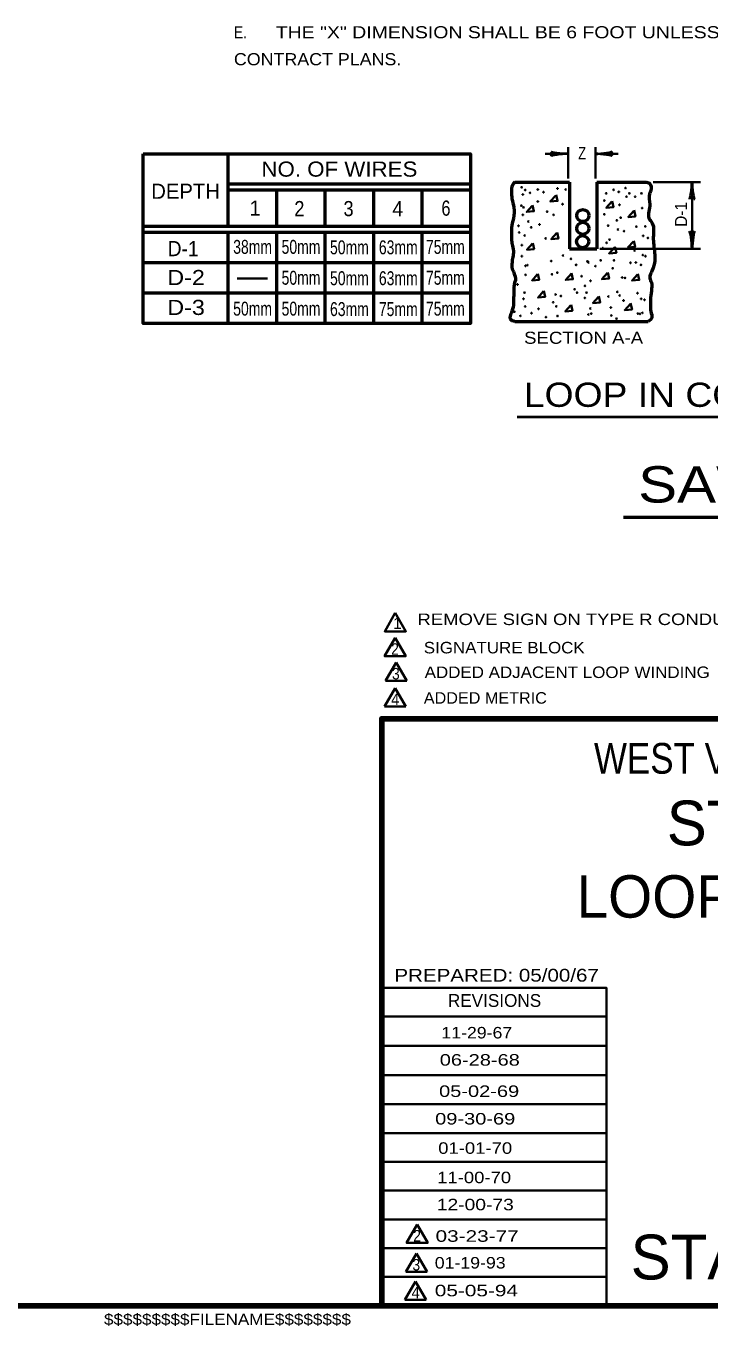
# Model space of a CAD drawing. Extents: x -90 to 623, y -379 to 75.
# Drawn here: x 376.8 to 489.7, y -372.3 to -157.7 of the extents above; entities that cross this region are included whole.
import ezdxf
from ezdxf.enums import TextEntityAlignment as Align

# ---------------------------------------------------------------- set-up
doc = ezdxf.new("R2010")
doc.units = 0
doc.header["$LTSCALE"] = 0.8
doc.layers.add('1', color=7, linetype='Continuous', lineweight=35)

msp = doc.modelspace()

# ---------------------------------------------------------------- linework, layer by layer
at = {"layer": '1'}
for p, q in [((466.3032, -182.8762), (466.3032, -177.7043)), ((470.8032, -182.8762), (470.8032, -177.7043)), ((462.4751, -178.8182), (466.2951, -178.8182)), ((470.7501, -178.8182), (474.5701, -178.8182)), ((480.2982, -183.5127), (488.1103, -183.5127)), ((486.7431, -183.4331), (486.7431, -194.4942)), ((471.5457, -194.493), (488.1103, -194.493)), ((411.6715, -199.4072), (416.6715, -199.4072)), ((437.8979, -262.8001), (436.1479, -265.8312)), ((439.6479, -265.8312), (437.8979, -262.8001)), ((436.1479, -265.8312), (439.6479, -265.8312)), ((437.7568, -267.038), (436.0068, -270.0691)), ((439.5068, -270.0691), (437.7568, -267.038)), ((436.0068, -270.0691), (439.5068, -270.0691)), ((472.6105, -321.2478), (435.5272, -321.2478)), ((472.6105, -326.0812), (435.5272, -326.0812)), ((472.6105, -330.9145), (435.5272, -330.9145)), ((472.6105, -335.7478), (435.5272, -335.7478)), ((472.6105, -340.4978), (435.5272, -340.4978)), ((472.6105, -345.2478), (435.5272, -345.2478)), ((472.6105, -349.9978), (435.5272, -349.9978)), ((472.6105, -354.7478), (435.5272, -354.7478)), ((472.6105, -359.4978), (435.5272, -359.4978)), ((441.2536, -360.3902), (439.5036, -363.4213)), ((443.0036, -363.4213), (441.2536, -360.3902)), ((472.6105, -364.2478), (435.5272, -364.2478)), ((439.5036, -363.4213), (443.0036, -363.4213)), ((441.1125, -364.977), (439.3625, -368.0081)), ((442.8625, -368.0081), (441.1125, -364.977)), ((439.3625, -368.0081), (442.8625, -368.0081))]:
    msp.add_line(p, q, dxfattribs=at)
at = {"layer": '1', "lineweight": 53}
for p, q in [((410.1558, -178.8394), (410.1558, -190.7343)), ((418.1558, -178.8394), (418.1558, -178.8787)), ((426.1558, -178.8394), (426.1558, -178.8787)), ((434.1558, -178.8394), (434.1558, -178.8787)), ((442.1558, -178.8394), (442.1558, -178.9583)), ((450.1558, -183.8394), (410.1597, -183.8394)), ((457.5023, -183.4934), (466.5023, -183.4934)), ((466.5023, -183.4934), (466.5023, -194.4934)), ((471.0023, -183.4934), (479.0023, -183.4934)), ((471.0023, -183.4934), (471.0023, -194.4934)), ((450.1558, -184.8394), (410.1597, -184.8394)), ((418.1558, -184.8463), (418.1558, -190.8138)), ((426.1558, -184.9259), (426.1558, -190.7343)), ((434.1558, -184.9259), (434.1558, -190.8138)), ((442.1558, -184.8463), (442.1558, -190.7343)), ((450.1558, -190.8394), (396.1558, -190.8394)), ((450.1558, -191.8394), (396.1558, -191.8394)), ((410.1558, -191.9278), (410.1558, -206.8394)), ((418.1558, -191.8483), (418.1558, -206.8394)), ((426.1558, -191.9278), (426.1558, -206.8394)), ((434.1558, -191.8483), (434.1558, -206.8394)), ((442.1558, -191.8483), (442.1558, -206.8394)), ((466.5023, -194.4934), (471.0023, -194.4934)), ((450.1558, -196.8394), (396.1558, -196.8394)), ((450.1558, -201.8394), (396.1558, -201.8394)), ((457.5023, -206.4934), (479.5023, -206.4934)), ((475.4047, -238.811), (566.749, -238.811))]:
    msp.add_line(p, q, dxfattribs=at)
at = {"layer": '1', "lineweight": 40}
msp.add_line((457.8999, -222.2609), (520.5994, -222.2609), dxfattribs=at)
at = {"layer": '1', "lineweight": 158}
msp.add_line((617.1938, -368.9978), (-42.4728, -368.9978), dxfattribs=at)
at = {"layer": '1', "lineweight": 53}
msp.add_lwpolyline([(396.1558, -178.8394), (450.1558, -178.8394), (450.1558, -206.8394), (396.1558, -206.8394)], close=True, dxfattribs=at)
at = {"layer": '1'}
for points in [[(464.2712, -185.679), (463.3498, -186.7155), (464.5398, -186.6003), (464.3095, -185.6022)], [(473.501, -186.7134), (472.5797, -187.7499), (473.7697, -187.6347), (473.5393, -186.6367)], [(460.3724, -187.3897), (459.4511, -188.4262), (460.6411, -188.3111), (460.4108, -187.313)], [(477.1213, -188.2252), (476.2, -189.2617), (477.39, -189.1465), (477.1597, -188.1484)], [(464.4303, -191.8852), (463.509, -192.9218), (464.699, -192.8066), (464.4687, -191.8085)], [(460.4122, -193.6358), (459.4908, -194.6722), (460.6808, -194.5571), (460.4505, -193.559)], [(473.9784, -194.2325), (473.0571, -195.269), (474.2471, -195.1538), (474.0168, -194.1557)], [(477.0816, -193.2777), (476.1602, -194.3142), (477.3502, -194.1991), (477.1199, -193.201)], [(461.2476, -198.6883), (460.3262, -199.7248), (461.5162, -199.6097), (461.2859, -198.6116)], [(466.8173, -198.6087), (465.896, -199.6453), (467.086, -199.5301), (466.8557, -198.532)], [(472.7849, -198.4894), (471.8636, -199.5259), (473.0536, -199.4108), (472.8232, -198.4127)], [(477.7578, -198.7281), (476.8365, -199.7646), (478.0265, -199.6494), (477.7962, -198.6513)], [(462.2423, -201.5129), (461.3209, -202.5494), (462.5109, -202.4342), (462.2806, -201.4362)], [(466.7378, -203.8204), (465.8164, -204.8569), (467.0064, -204.7417), (466.7761, -203.7437)], [(471.3129, -202.428), (470.3916, -203.4645), (471.5816, -203.3493), (471.3512, -202.3512)], [(476.5643, -203.5817), (475.643, -204.6182), (476.833, -204.503), (476.6027, -203.5049)], [(472.6105, -368.9978), (472.6105, -316.4978), (435.5272, -316.4978)]]:
    msp.add_lwpolyline(points, dxfattribs=at)
for points in [[(437.7648, -254.6303), (436.0148, -257.6614), (439.5148, -257.6614)], [(437.7527, -258.7338), (436.0027, -261.7649), (439.5027, -261.7649)], [(441.3798, -355.5983), (439.6298, -358.6294), (443.1298, -358.6294)]]:
    msp.add_lwpolyline(points, close=True, dxfattribs=at)
at = {"layer": '1', "lineweight": 158}
msp.add_lwpolyline([(435.5272, -368.9978), (435.5272, -272.0812), (617.1938, -272.0812)], dxfattribs=at)
at = {"layer": '1'}
for centre in [(458.6103, -184.3565), (464.538, -184.5554), (475.757, -184.4758), (458.8092, -185.55), (459.207, -184.7941), (460.0027, -185.2715), (461.2757, -184.7146), (461.2757, -186.7037), (462.2305, -185.1522), (465.8907, -184.7146), (472.256, -186.5446), (472.5743, -185.3511), (473.8076, -184.7543), (474.6431, -185.1124), (475.9162, -185.9081), (476.3936, -185.3511), (477.3483, -185.9081), (478.3827, -185.3511), (458.5704, -187.3801), (458.8092, -188.8918), (458.9285, -187.6586), (462.8273, -188.3747), (463.9014, -188.8918), (465.3734, -187.1413), (472.256, -188.8123), (474.7624, -187.2607), (478.5021, -187.7779), (458.093, -190.7219), (459.7242, -190.0058), (460.2016, -190.9606), (461.5542, -190.4832), (472.8926, -190.6821), (474.3247, -189.8068), (474.9613, -189.3692), (477.5472, -190.8413), (479.0192, -190.8015), (458.2124, -191.7961), (459.1274, -192.3132), (462.5886, -192.7907), (473.1312, -192.9896), (474.5238, -191.3187), (475.5183, -191.5972), (478.6612, -192.353), (479.4569, -192.7111), (458.65, -193.9046), (472.0173, -194.382), (472.6538, -193.5067), (477.2688, -194.7798), (458.65, -195.7347), (459.2467, -197.326), (459.565, -197.2067), (463.5036, -196.5303), (465.453, -195.6153), (466.7659, -196.1722), (467.6013, -197.1668), (469.4712, -196.5701), (469.6303, -196.769), (470.784, -197.3657), (471.6592, -196.411), (473.8474, -196.411), (476.5925, -196.8088), (477.4677, -196.769), (478.3032, -197.1668), (478.6214, -195.5358), (479.0591, -195.7347), (459.2865, -198.798), (463.623, -198.7184), (464.4982, -198.4399), (468.5163, -199.0367), (473.6485, -197.7238), (475.2, -199.2356), (475.6774, -199.3152), (457.9339, -200.3893), (459.0876, -201.742), (467.3627, -201.185), (467.7605, -201.742), (469.0733, -200.628), (469.312, -201.742), (469.9883, -199.7926), (474.4043, -201.6227), (458.9285, -202.7763), (463.8219, -203.3333), (464.2197, -202.0602), (465.095, -202.2989), (469.0336, -202.6172), (472.9323, -202.3785), (474.8022, -202.2194), (475.4387, -203.0548), (477.7462, -201.8216), (478.3429, -202.7763), (478.8999, -202.9355), (457.4167, -204.8849), (458.4113, -205.5613), (459.207, -204.0097), (460.2413, -205.1236), (461.3951, -204.4075), (462.6283, -205.7999), (464.3391, -204.0097), (464.538, -205.601), (469.6303, -205.3623), (469.9486, -204.3678), (470.1078, -205.2032), (473.3302, -204.2086), (473.4097, -205.5214), (474.285, -206.0387), (477.786, -205.2032), (478.144, -205.2429), (478.5418, -205.0838)]:
    msp.add_circle(centre, 0.0607, dxfattribs=at)
at = {"layer": '1', "lineweight": 53}
for centre in [(468.7212, -189.0232), (468.7212, -191.1317), (468.6814, -193.3198)]:
    msp.add_circle(centre, 1, dxfattribs=at)
at = {"layer": '1', "lineweight": 40}
for centre, major_axis, ratio, start_param, end_param in [((465.2039, -179.0945), (1.7857, 0.1562), 0.122415, 0.89635335, 3.14159265), ((465.1746, -178.6066), (1.7565, -0.1757), 0.07063, 3.14071475, 5.41810995), ((471.8706, -179.0298), (1.7565, -0.1757), 0.07063, 6.28230741, 8.55970261), ((471.8413, -178.5419), (-1.7857, -0.1562), 0.122415, 0.89635335, 3.14159265), ((486.5315, -184.5536), (-0.1757, -1.7565), 0.07063, 6.28230741, 8.55970261), ((487.0194, -184.5243), (-0.1562, 1.7857), 0.122415, 0.89635335, 3.14159265), ((486.4668, -193.403), (0.1562, -1.7857), 0.122415, 0.89635335, 3.14159265), ((486.9547, -193.3737), (0.1757, 1.7565), 0.07063, 6.28230741, 8.55970261)]:
    msp.add_ellipse(centre, major_axis=major_axis, ratio=ratio, start_param=start_param, end_param=end_param, dxfattribs=at)
at = {"layer": '1', "lineweight": 53}
for points in [[(457.5023, -183.4934), (457.1043, -184.0104), (456.9452, -185.0447), (457.0247, -186.2382), (457.343, -187.6705), (457.2635, -189.5006), (456.9452, -191.0123), (456.9452, -191.5693), (456.9452, -193.1607), (457.1043, -194.0359), (457.2635, -195.1498), (457.1043, -196.1047), (457.0247, -196.9799), (457.0247, -197.6164), (457.343, -198.4917), (457.5817, -199.6852), (457.4226, -200.2422), (457.343, -200.8787), (457.343, -201.8335), (457.2635, -202.7087), (457.2635, -203.8227), (456.8656, -205.1753), (456.7065, -206.0506), (457.5023, -206.4934)], [(479.0023, -183.4934), (479.7015, -183.6922), (479.9402, -184.8857), (479.7015, -185.4426), (479.781, -187.1135), (479.6219, -189.421), (480.1788, -190.2962), (480.338, -192.6037), (480.4176, -193.8767), (480.5767, -196.5025), (480.1788, -198.0143), (479.781, -199.3669), (480.0197, -200.083), (480.0197, -201.4357), (479.8606, -202.9474), (479.8606, -203.8227), (479.9402, -204.8571), (480.0993, -205.8914), (479.5023, -206.4934)]]:
    msp.add_spline(points, degree=3, dxfattribs=at)

# ---------------------------------------------------------------- texts
at = {"layer": '1'}
for s, height, width, p in [('E.', 2, 0.85, (411.1331, -159.7506)), ('THE "X" DIMENSION SHALL BE 6 FOOT UNLESS OTHERWISE SPECIFIED ON THE', 2, 1.2, (418.0359, -159.7507)), ('CONTRACT PLANS.', 2, 1.1, (411.1331, -164.2022)), ('38mm', 2.3, 0.75, (411.0119, -195.3366)), ('50mm', 2.3, 0.75, (419.0018, -195.3367)), ('50mm', 2.3, 0.75, (426.9919, -195.4107)), ('63mm', 2.3, 0.75, (435.0559, -195.4107)), ('75mm', 2.3, 0.75, (442.8241, -195.3367)), ('50mm', 2.3, 0.75, (419.0018, -200.4367)), ('50mm', 2.3, 0.75, (426.9919, -200.5107)), ('63mm', 2.3, 0.75, (435.0559, -200.5107)), ('75mm', 2.3, 0.75, (442.8241, -200.4367)), ('50mm', 2.3, 0.75, (411.0119, -205.5366)), ('50mm', 2.3, 0.75, (419.0018, -205.5367)), ('63mm', 2.3, 0.75, (426.9919, -205.6107)), ('75mm', 2.3, 0.75, (435.0559, -205.6107)), ('75mm', 2.3, 0.75, (442.8241, -205.5367)), ('REMOVE SIGN ON TYPE R CONDUIT ON TYPICAL GUTTER AND SIDEWALK PLAN.', 1.9, 1.2, (441.4286, -256.6228)), ('2', 1.9, 0.9, (437.0812, -261.5374)), ('SIGNATURE BLOCK', 1.9, 1.1, (442.4683, -261.3007)), ('3', 1.9, 0.9, (437.2263, -265.6037)), ('ADDED ADJACENT LOOP WINDING', 1.9, 1.1, (442.6135, -265.367)), ('4', 1.9, 0.95, (437.0852, -269.8416)), ('ADDED METRIC', 1.9, 1.05, (442.4723, -269.6049)), ('PREPARED: 05/00/67', 2.114, 1.2, (437.6105, -315.4978)), ('11-29-67', 1.9, 1.15, (445.3687, -324.8756)), ('06-28-68', 1.9, 1.3, (445.1004, -329.3649)), ('05-02-69', 1.9, 1.3, (444.99, -334.5331)), ('09-30-69', 1.9, 1.3, (444.343, -339.0852)), ('01-01-70', 1.9, 1.2, (444.8479, -343.9215)), ('11-00-70', 1.9, 1.2, (444.6744, -348.7741)), ('12-00-73', 1.9, 1.25, (444.6113, -353.2477)), ('2', 1.9, 0.9, (440.7202, -358.3997)), ('03-23-77', 1.9, 1.35, (444.4061, -358.4469)), ('3', 1.9, 0.9, (440.5939, -363.1916)), ('01-19-93', 1.9, 1.15, (444.2798, -362.8592)), ('4', 1.9, 0.95, (440.4528, -367.7783)), ('05-05-94', 1.9, 1.35, (444.2799, -367.4459)), ('$$$$$$$$$FILENAME$$$$$$$$', 1.833, 1.15, (389.6938, -372.1645))]:
    msp.add_text(s, height=height, dxfattribs=dict(at, width=width)).set_placement(p)
for s, height, width, p in [('Z', 2, 0.8, (468.6017, -179.7185)), ('NO. OF WIRES', 2.5, 1.1, (428.5398, -182.5953)), ('2', 2.5, 0.9, (421.9357, -189.1198)), ('3', 2.5, 0.9, (430.0516, -189.1198)), ('4', 2.5, 0.95, (438.1674, -189.1198)), ('6', 2.5, 0.8, (446.1242, -189.0403)), ('D-1', 2.5, 0.95, (402.76, -195.724)), ('D-2', 2.5, 1.15, (403.2375, -200.498)), ('D-3', 2.5, 1.15, (403.2375, -205.4313)), ('SECTION A-A', 2, 1.15, (468.8405, -210.1928)), ('LOOP IN CONCRETE', 4, 1.15, (489.5678, -220.6008)), ('SAW SLOT DETAIL', 6, 1.2, (520.9174, -236.4004)), ('WEST VIRGINIA DIVISION OF HIGHWAYS', 5.074, 0.85, (527.1105, -281.1645))]:
    msp.add_text(s, height=height, dxfattribs=dict(at, width=width)).set_placement(p, align=Align.CENTER)
for s, height, p in [('DEPTH', 2.5, (403.1577, -186.2554)), ('1', 2.5, (414.6215, -189.0403)), ('STANDARD DETAIL', 7.401, (528.4855, -292.9978)), ('LOOP DETECTOR TYPE III', 7, (526.4484, -304.9311))]:
    msp.add_text(s, height=height, dxfattribs=at).set_placement(p, align=Align.CENTER)
at = {"layer": '1', "width": 0.95}
msp.add_text('D-1', height=2, rotation=90, dxfattribs=at).set_placement((485.9132, -188.8236), align=Align.CENTER)
at = {"layer": '1'}
for s, height, p in [('1', 1.9, (437.4119, -257.2844)), ('REVISIONS', 2.114, (446.4438, -319.6645)), ('STANDARD SHEET TES-01', 7.401, (476.6105, -364.6645))]:
    msp.add_text(s, height=height, dxfattribs=at).set_placement(p)

doc.saveas('drawing.dxf')
